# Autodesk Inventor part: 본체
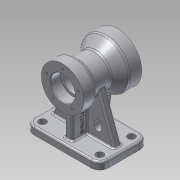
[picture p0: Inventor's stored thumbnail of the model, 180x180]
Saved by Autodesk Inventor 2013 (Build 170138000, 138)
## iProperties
Created: 2015-08
Part Number: 본체
Material: 알루미늄 6061
Document SubType Name: Modeling
Designer: ST
Density: 2.71 g/cm^3
Mass: 1062.52 g
Surface Area: 750.327 cm^2
Volume: 392.074 cm^3
Author: ST
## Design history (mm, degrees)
sketch "스케치1"
  geometry: L1 (-61, 40)-(61, 40); L2 (61, 40)-(61, -40); L3 (61, -40)-(-61, -40); L4 (-61, -40)-(-61, 40); 1 further point
  constraints: 8 end point, 2 parallel, 1 horizontal, 1 perpendicular
  dimensions: "d0" = 122 distance between parallel lines of L2 L4; "d2" = 61 distance from line of point (0, 0) L4; "d3" = 80 distance between parallel lines of L3 L1; "d4" = 40 distance from line of point (0, 0) L1
extrude "돌출1" new body sketch "스케치1" distance "d5" = 12; taper "d6" = 0 deg
sketch "스케치4"
  geometry: L1 (-40, 90)-(50, 90); L2 (-40, 125)-(-20, 125); L3 (-20, 125)-(-14.804, 116); L4 (-14.804, 116)-(13.315, 116); L5 (13.315, 116)-(30, 130); L6 (30, 130)-(50, 130); L7 (50, 130)-(50, 90); L8 (-40, 125)-(-40, 90); L9 (-40, 0)-(-40, 12) reference; 1 further point
  constraints: 16 end point, 4 parallel, 1 horizontal, 1 perpendicular
  dimensions: "d8" = 90 distance from line of point (0, 0) L1; "d10" = 70 diameter of L2 L1; "d11" = 80 diameter of L6 L1; "d12" = 52 diameter of L4 L1; "d13" = 90 distance between parallel lines of L7 L8; "d14" = 60 deg angle of L4 L3; "d15" = 40 deg angle of L4 L5; "d16" = 20 distance of L2.start L2.end; "d17" = 20 distance of L5.end L6.end; "d18" = 0 distance between parallel lines of L9 L8
revolve "회전1" sketch "스케치4" stored, may be unused: angle "d19" = 90 deg
fillet "모깎기1" dims "d20" = 14
sketch "스케치5"
  geometry: L1 (-30, 11.583)-(-30, 57.618); L2 (-40, 0)-(-40, 12) reference; L3 (30, 9.004)-(30, 12); L4 (40, 12)-(40, 0) reference; L5 (26, 12)-(40, 12) reference; L6 (30, 12)-(37.543, 54.776); L7 (-8.897, 12)-(-8.897, 64); L8 (1.694, 64)-(1.694, 12); L9 (-14.804, 64)-(13.315, 64) reference; L10 (-8.897, 64)-(1.694, 64); L11 (-8.897, 12)-(1.694, 12); 1 further point
  constraints: 14 end point, 3 point on line, 2 parallel, 1 collinear, 1 perpendicular, 1 vertical
  dimensions: "d21" = 10 distance between parallel lines of L1 L2; "d22" = 10 distance between parallel lines of L4 L3; "d23" = 80 deg angle of L5 L6; "d24" = 12 vertical distance of point (0, 0) L7.start; "d25" = 12 vertical distance of point (0, 0) L8.end
sketch "스케치6"
  geometry: L1 (-6, 6)-(6, 6); L2 (6, 6)-(6, -6); L3 (6, -6)-(-6, -6); L4 (-6, -6)-(-6, 6); 1 further point
  constraints: 8 end point, 2 parallel, 1 horizontal, 1 perpendicular
  dimensions: "d26" = 12 distance between parallel lines of L2 L4; "d28" = 6 distance from line of point (0, 0) L4; "d29" = 12 distance between parallel lines of L3 L1; "d30" = 6 distance from line of point (0, 0) L1
extrude "돌출2" join sketch "스케치6" stored distance "d31" = 12; taper "d32" = 0 deg
feature "리브1" dims "d33" = 1, "d34" = 12, "d35" = 0, "d36" = 0, "d37" = 1, "d38" = 1
feature "리브2" dims "d39" = 1, "d40" = 12, "d41" = 0, "d42" = 0, "d43" = 1, "d44" = 1
sketch "스케치7"
  geometry: L1 (51, 12)-(23.395, 87.843); L2 (47, 12)-(61, 12) reference; L3 (61, 12)-(61, 0) reference; 1 further point
  constraints: 2 end point
  dimensions: "d45" = 0 distance from line of L1.start L2; "d46" = 10 distance from line of L3 L1.start; "d47" = 70 deg angle of L2 L1
feature "리브3" sketch "스케치7" dims "d48" = 1, "d49" = 12, "d50" = 0, "d51" = 0, "d52" = 1, "d53" = 1
fillet "모깎기2" dims "d54" = 5
sketch "스케치8"
  geometry: C1 r 40 at (0, 0) reference; C2 r 26 at (0, 0); 1 further point
  constraints: 1 centre point, 1 coincident
  dimensions: "d55" = 52 diameter of C2
extrude "돌출3" cut sketch "스케치8" distance "d57" = 20; taper "d58" = 0 deg
sketch "스케치9"
  geometry: C1 r 26 at (0, 0) reference; C2 r 19 at (0, 0); 1 further point
  constraints: 1 centre point, 1 coincident
  dimensions: "d59" = 38 diameter of C2
extrude "돌출4" cut sketch "스케치9" distance "d61" = 3; taper "d62" = 0 deg
sketch "스케치10"
  geometry: C1 r 35 at (0, 0) reference; C2 r 20 at (0, 0); 1 further point
  constraints: 1 centre point, 1 coincident
  dimensions: "d63" = 40 diameter of C2
extrude "돌출5" cut sketch "스케치10" distance "d65" = 17; taper "d66" = 0 deg
sketch "스케치11"
  geometry: C1 r 20 at (0, 0) reference; C2 r 16 at (0, 0); 1 further point
  constraints: 1 centre point, 1 coincident
  dimensions: "d67" = 32 diameter of C2
extrude "돌출6" cut sketch "스케치11" stored distance "d69" = 17; taper "d70" = 0 deg
fillet "모깎기3" dims "d71" = 3
fillet "모깎기4" dims "d72" = 3
fillet "모깎기5" dims "d73" = 3
fillet "모깎기6" dims "d74" = 3
fillet "모깎기7" dims "d75" = 0.3
chamfer "모따기1" distance "d76" = 1; stored, may be unused: second distance "d77" = 2, angle "d78" = 45 deg
sketch "스케치12"
  geometry: C1 r 6 at (-47, -26); A1 r 14 centre (-47, -26) between (-61, -26) and (-47, -40) reference; 1 further point
  constraints: 1 centre point, 1 coincident
  dimensions: "d79" = 12 diameter of C1
extrude "돌출7" cut sketch "스케치12" distance "d81" = 17; taper "d82" = 0 deg
sketch "스케치13"
  geometry: C1 r 6 at (-47, 26); C2 r 6 at (47, 26); C3 r 6 at (47, -26); A1 r 14 centre (47, -26) between (47, -40) and (61, -26) reference; A2 r 14 centre (47, 26) between (61, 26) and (47, 40) reference; A3 r 14 centre (-47, 26) between (-47, 40) and (-61, 26) reference; 1 further point
  constraints: 3 centre point, 3 coincident, 2 equal radius
  dimensions: "d83" = 12 diameter of C1
extrude "돌출8" cut sketch "스케치13" distance "d85" = 17; taper "d86" = 0 deg
sketch "스케치14"
  geometry: L1 (38, 15)-(-56, 15) reference; L2 (21, -21)-(21, -15); L3 (9, -21)-(9, -15); A1 r 6 centre (15, -15) between (21, -15) and (9, -15); A2 r 6 centre (15, -21) between (9, -21) and (21, -21); 1 further point
  constraints: 4 end point, 4 point on circle, 4 tangent, 2 centre point
  dimensions: "d87" = 30 distance from line of L1 A1.centre; "d88" = 24 horizontal distance of point (-9, 15) A1.centre; "d89" = 12 diameter of A1; "d90" = 12 diameter of A2; "d91" = 0 horizontal distance of A1.centre A2.centre; "d92" = 6 distance of A1.centre A2.centre
extrude "돌출9" cut sketch "스케치14" distance "d93" = 17; taper "d94" = 0 deg
sketch "스케치15" dims "d95" = 66
  geometry: C1 r 40 at (0, 0) reference; C2 r 27 at (0, 0) reference; 7 further points
  constraints: 1 coincident, 1 vertical alignment, 8 other
  dimensions: "d99" = 360 deg dimension on C1.centre point (0, -33) (derived)
hole "구멍1" sketch "스케치15" at (0, -33), (31.385, -10.198), (19.397, 26.698), (-19.397, 26.698), (-31.385, -10.198) diameter "d101" = 3.242; stored, may be unused: countersink angle "d105" = 90 deg, drill point angle "d107" = 118 deg; dims "d102" = 10, "d103" = 4, "d104" = 2, "d106" = 13
sketch "스케치16" dims "d108" = 54
  geometry: C1 r 35 at (0, 0) reference; C2 r 21 at (0, 0) reference; 7 further points
  constraints: 1 coincident, 1 vertical alignment, 8 other
  dimensions: "d112" = 360 deg dimension on C1.centre point (0, 27) (derived)
hole "구멍2" sketch "스케치16" at (0, 27), (-25.679, 8.343), (-15.87, -21.843), (15.87, -21.843), (25.679, 8.343) diameter "d114" = 3.242; stored, may be unused: countersink angle "d118" = 90 deg, drill point angle "d120" = 118 deg; dims "d115" = 10, "d116" = 4, "d117" = 2, "d119" = 13
node "작업 평면2"
sketch "스케치17"
  geometry: L1 (-0.261, 9.998)-(-41.739, 9.998); L2 (-41.739, 9.998)-(-41.739, 16.002); L3 (-41.739, 16.002)-(-0.261, 16.002); L4 (-0.261, 16.002)-(-0.261, 9.998); L5 (-0.261, 13)-(-41.739, 13); L6 (-21, 9.998)-(-21, 16.002); L7 (3, 1)-(3, 53) reference; L8 (-37.119, -3)-(0, -3) reference; 1 further point
  constraints: 4 end point, 4 midpoint, 2 other
  dimensions: "d122" = 24 distance between parallel lines of L7 L6; "d123" = 16 distance between parallel lines of L5 L8
feature "엠보싱1" sketch "스케치17" dims "d0" = 122, "d2" = 61, "d3" = 80, "d4" = 40, "d124" = 0.5, "d125" = 0
fillet "모깎기8" dims "d126" = 3
node "솔리드1"
mirror "대칭1"
mirror "대칭2"
other parameters: "d121" = 23.25
